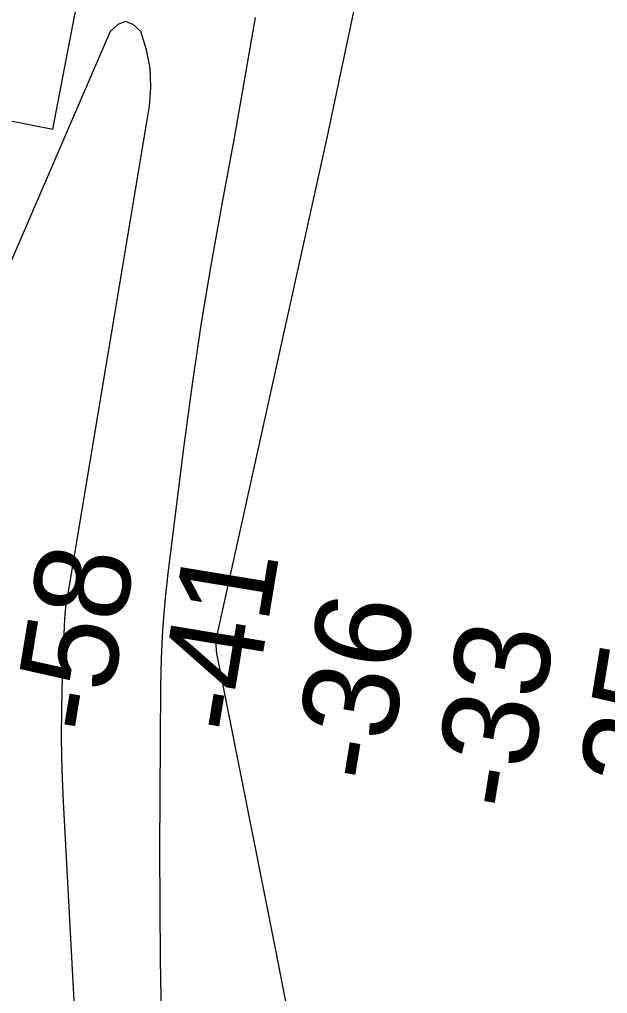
# Model space of a CAD drawing. Extents: x 3187622 to 3225504, y 800805 to 826213.
# Drawn here: x 3197502 to 3197916, y 822602 to 823287 of the extents above; entities that cross this region are included whole.
import ezdxf

# ---------------------------------------------------------------- set-up
doc = ezdxf.new("R2010")
doc.units = 0
for name, color, linetype in [('V-RIVR-RANG', 7, 'Continuous'), ('V-RRAP-RVMT', 7, 'Continuous'), ('V-TOPO-MAJR', 7, 'Continuous'), ('V-TOPO-MINR', 7, 'Continuous')]:
    doc.layers.add(name, color=color, linetype=linetype)

msp = doc.modelspace()

# ---------------------------------------------------------------- linework, layer by layer
at = {"layer": 'V-RRAP-RVMT'}
for p, q in [((3197525.541000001, 823209.9119999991), (3197546.729000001, 823320.3069999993)), ((3197493.3316735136, 823216.1226858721), (3197525.541000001, 823209.9119999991))]:
    msp.add_line(p, q, dxfattribs=at)
at = {"layer": 'V-TOPO-MAJR'}
msp.add_lwpolyline([(3197690.796866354, 822589.1811564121), (3197682.2096360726, 822633.5430304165), (3197641.3142845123, 822838.7336858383), (3197640.8994218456, 822841.1183314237), (3197640.6017518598, 822843.5204218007), (3197640.4322977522, 822847.1424997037), (3197640.5883618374, 822851.3753472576), (3197640.6794947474, 822851.8987343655), (3197718.4346230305, 823203.7093066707), (3197737.3124425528, 823292.5167432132), (3197755.2318945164, 823381.5091272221), (3197771.713795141, 823470.7789324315), (3197787.237328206, 823560.2336851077), (3197812.3359122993, 823712.1265437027), (3197814.491296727, 823725.7876546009), (3197816.5138821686, 823739.4674142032), (3197818.33726913, 823753.1751468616), (3197820.027857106, 823766.901528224), (3197821.837291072, 823780.6047072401), (3197823.937360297, 823794.2584094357), (3197826.4733824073, 823807.8378964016), (3197829.3000397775, 823821.367906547), (3197845.351592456, 823892.491011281)], dxfattribs=at)
at = {"layer": 'V-TOPO-MINR'}
for points in [[(3197602.6739436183, 822548.0476358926), (3197601.2010654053, 822625.4768689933), (3197600.827045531, 822702.9387112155), (3197601.4967186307, 822817.9980184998), (3197601.969310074, 822837.931347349), (3197602.915749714, 822857.8336451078), (3197604.572961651, 822877.6893962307), (3197606.7040217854, 822897.5141162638), (3197618.003305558, 822987.4604418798), (3197623.835781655, 823030.6389290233), (3197630.2016676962, 823073.7335472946), (3197637.367668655, 823116.7023622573), (3197645.0670795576, 823159.5873083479), (3197652.985678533, 823202.4409413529), (3197660.6627311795, 823245.3367526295), (3197667.9774643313, 823288.2958313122)], [(3197540.5679845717, 822596.911950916), (3197538.8788215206, 822627.5559672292), (3197537.2130702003, 822658.201242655), (3197535.5824364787, 822688.8484067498), (3197533.9752144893, 822719.496829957), (3197533.0838393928, 822736.6829131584), (3197532.230194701, 822758.7415719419), (3197531.7630399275, 822780.8033362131), (3197531.875620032, 822802.8697587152), (3197532.374690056, 822824.939286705), (3197533.646071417, 822860.487449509), (3197533.8829524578, 822864.7768479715), (3197534.2303419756, 822869.0551107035), (3197534.743494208, 822873.3166698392), (3197535.367154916, 822877.567093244), (3197593.435791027, 823226.0654492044), (3197594.506113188, 823239.4608358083), (3197594.097294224, 823252.6847413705), (3197591.469763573, 823265.6514253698), (3197587.363091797, 823278.4466283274), (3197582.02600554, 823283.4491708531), (3197576.671910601, 823285.6114829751), (3197571.2923026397, 823283.513449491), (3197565.8956859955, 823278.5751856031), (3197416.5236298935, 822932.9353806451)]]:
    msp.add_lwpolyline(points, dxfattribs=at)

# ---------------------------------------------------------------- texts
at = {"layer": 'V-RIVR-RANG'}
for s, p in [('-58', (3197562.3180443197, 822782.5195504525)), ('-41', (3197663.6421672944, 822782.3241846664)), ('-36', (3197759.373973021, 822748.2975578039)), ('-33', (3197857.4717591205, 822728.5835798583)), ('-35', (3197956.34486607, 822713.5550688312))]:
    msp.add_text(s, height=67, rotation=80.61413888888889, dxfattribs=at).set_placement(p)

doc.saveas('drawing.dxf')
